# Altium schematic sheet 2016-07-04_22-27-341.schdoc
size 234 x 111 mm; SheetNumber: 1; SheetTotal: 1
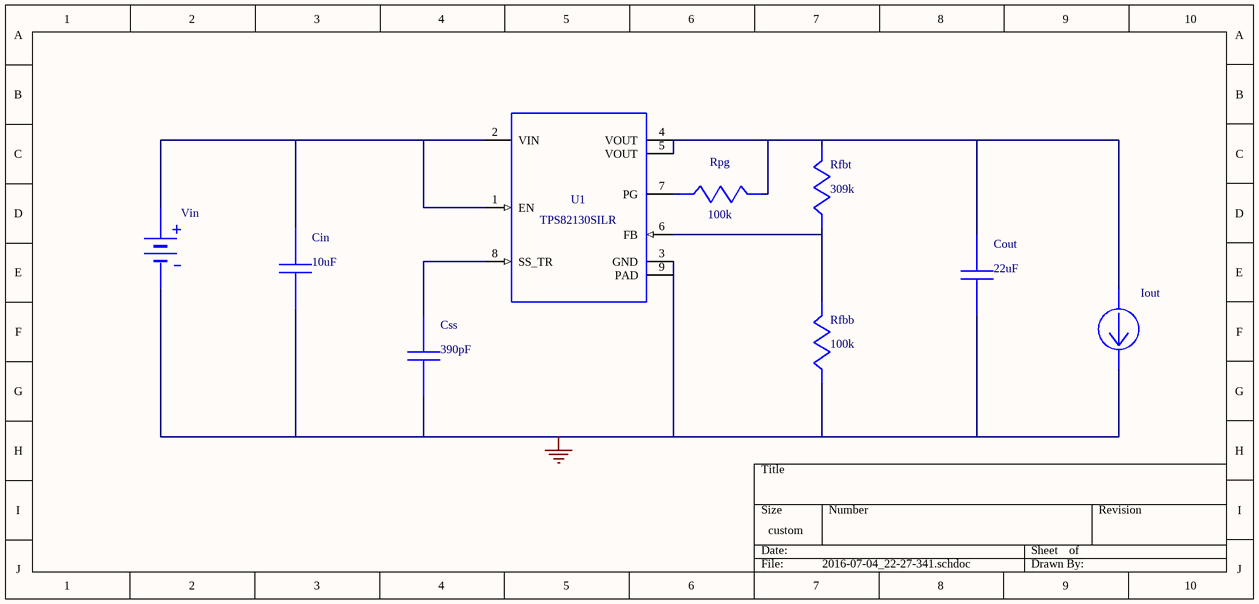
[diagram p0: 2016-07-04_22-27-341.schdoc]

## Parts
Cin  value 10uF  (hidden comment: TMK316BJ106KL-T)
Cout  value 22uF  (hidden comment: JMK212BJ226MG-T)
Css  value 390pF  (hidden comment: GRM1555C1E391JA01D)
Iout  WB_CURRENT_LOAD  (value not drawn)
Rfbb  value 100k  (hidden comment: CRCW0402100KFKED)
Rfbt  value 309k  (hidden comment: CRCW0402309KFKED)
Rpg  value 100k  (hidden comment: CRCW0402100KFKED)
U1  TPS82130SILR
Vin  WB_BATTERY  (value not drawn)

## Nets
0: Cin.2 Cout.2 Css.2 Iout.2(-) Rfbb.2 U1.3(GND) U1.9(PAD) Vin.2(-)
NetCin_1: Cin.1 U1.1(EN) U1.2(VIN) Vin.1(+)
NetCout_1: Cout.1 Iout.1(+) Rfbt.1 Rpg.1 U1.4(VOUT) U1.5(VOUT)
NetCss_1: Css.1 U1.8(SS_TR)
NetRfbb_1: Rfbb.1 Rfbt.2 U1.6(FB)
NetRpg_2: Rpg.2 U1.7(PG)

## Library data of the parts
Cin = TMK316BJ106KL-T: Manufacturer Name: Taiyo Yuden
Cout = JMK212BJ226MG-T: Manufacturer Name: Taiyo Yuden
Css = GRM1555C1E391JA01D: GRM1555C1E391JA0; Manufacturer Name: MuRata
Rfbb Rpg = CRCW0402100KFKED: Manufacturer Name: Vishay-Dale
Rfbt = CRCW0402309KFKED: Manufacturer Name: Vishay-Dale
U1 = TPS82130SILR: Manufacturer Name: Texas Instruments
